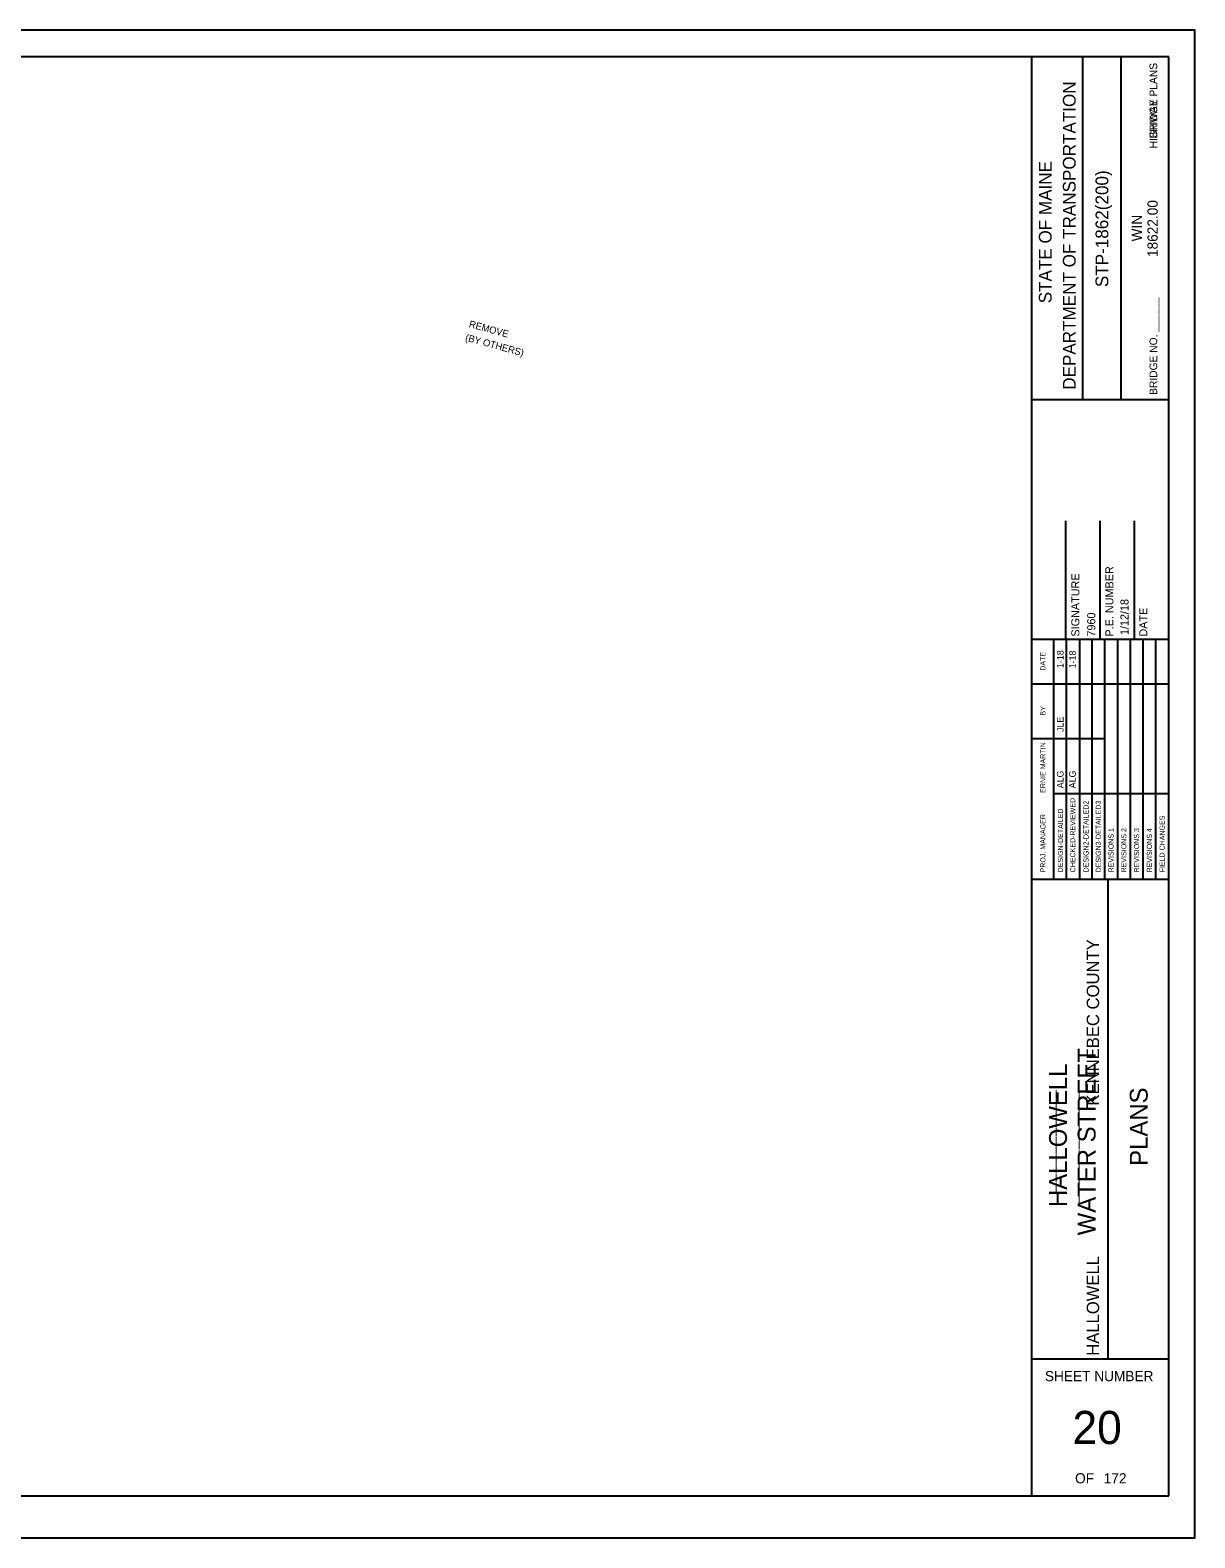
# Model space of a CAD drawing. Extents: x 0 to 850, y 0 to 550.
# Drawn here: x 425 to 850, y 0 to 550 of the extents above; entities that cross this region are included whole.
import ezdxf

# ---------------------------------------------------------------- set-up
doc = ezdxf.new("R2010")
doc.units = 0
for name, color, linetype in [('ANNOTATION', 7, 'Continuous'), ('BORDER', 7, 'Continuous'), ('BRIDGE_TITLE', 7, 'Continuous'), ('Default', 7, 'Continuous'), ('HIGHWAY_TITLE', 7, 'Continuous'), ('PLOT BOUNDARY', 7, 'Continuous')]:
    doc.layers.add(name, color=color, linetype=linetype)

msp = doc.modelspace()

# ---------------------------------------------------------------- linework, layer by layer
at = {"layer": 'BORDER'}
for p, q in [((840.33, 540.24), (40.33, 540.24)), ((790.33, 15.26), (790.33, 540.26)), ((808.97, 415.23), (808.97, 540.23)), ((822.95, 415.23), (822.95, 540.23)), ((840.33, 15.26), (840.33, 540.26)), ((790.34, 415.22), (840.33, 415.22)), ((802.83, 327.76), (802.83, 371)), ((815.33, 327.76), (815.33, 371)), ((827.83, 327.76), (827.83, 371)), ((790.33, 327.76), (840.33, 327.76)), ((790.33, 240.26), (840.33, 240.26)), ((818.29, 65.26), (818.29, 240.26)), ((790.33, 65.26), (840.33, 65.26)), ((40.33, 15.24), (840.33, 15.24))]:
    msp.add_line(p, q, dxfattribs=at)
for points in [[(798.41, 311.51), (798.41, 327.76)], [(803.07, 240.27), (803.07, 327.76)], [(807.73, 327.76), (807.73, 240.27)], [(812.39, 240.27), (812.39, 327.76)], [(817.04, 240.27), (817.04, 327.76)], [(821.7, 240.27), (821.7, 327.76)], [(826.36, 240.27), (826.36, 327.76)], [(831.02, 240.27), (831.02, 327.76)], [(835.68, 240.27), (835.68, 327.76)], [(798.41, 240.27), (798.41, 324.23)], [(790.33, 311.51), (840.33, 311.51)], [(790.33, 291.51), (798.41, 291.51)], [(798.41, 291.51), (817.04, 291.51)], [(798.41, 271.51), (840.33, 271.51)]]:
    msp.add_lwpolyline(points, dxfattribs=at)
at = {"layer": 'Default'}
msp.add_lwpolyline([(40.33, 15.24), (790.33, 15.24), (790.33, 540.26), (40.33, 540.26)], close=True, dxfattribs=at)
at = {"layer": 'PLOT BOUNDARY'}
msp.add_lwpolyline([(-0.13, -0.05), (849.87, -0.05), (849.87, 549.95), (-0.13, 549.95)], close=True, dxfattribs=at)

# ---------------------------------------------------------------- texts
at = {"layer": 'ANNOTATION'}
for s, p in [('REMOVE', (584.78, 441.66)), ('(BY OTHERS)', (583.44, 436.73))]:
    msp.add_text(s, height=2.55, rotation=344.7241, dxfattribs=at).set_placement(p)
at = {"layer": 'BORDER'}
for s, height, p in [('DEPARTMENT OF TRANSPORTATION', 4.6588, (806.37, 418.77)), ('STATE OF MAINE', 4.6588, (797.61, 450.3)), ('STP-1862(200)', 4.6588, (818.29, 456.21)), ('18622.00', 3.726, (836.31, 467.18)), ('WIN', 3.726, (830.52, 472.89)), ('P.E. NUMBER', 2.9528, (820.14, 328.72)), ('SIGNATURE', 2.953, (807.73, 328.72)), ('1/12/18', 2.953, (825.66, 329.26)), ('7960', 2.953, (813.54, 328.72)), ('DATE', 2.953, (832.54, 328.72)), ('DATE', 1.857, (795.35, 316.29)), ('1-18', 2.423, (801.95, 317.25)), ('1-18', 2.423, (806.42, 317.14)), ('BY', 1.857, (795.35, 299.93)), ('JLE', 2.423, (801.95, 293.93)), ('ERNIE MARTIN', 1.8637, (795.35, 271.72)), ('ALG', 2.423, (801.95, 273.38)), ('ALG', 2.423, (806.42, 273.38)), ('DESIGN-DETAILED', 1.8637, (801.76, 242.7)), ('CHECKED-REVIEWED', 1.8637, (806.24, 242.7)), ('DESIGN2-DETAILED2', 1.8637, (811.08, 242.7)), ('DESIGN3-DETAILED3', 1.8637, (815.55, 242.7)), ('PROJ. MANAGER', 1.8637, (795.35, 242.7)), ('FIELD CHANGES', 1.8637, (838.85, 242.7)), ('REVISIONS 1', 1.8637, (820.21, 242.7)), ('REVISIONS 2', 1.8637, (824.87, 242.7)), ('REVISIONS 3', 1.8637, (829.53, 242.7)), ('REVISIONS 4', 1.8637, (834.19, 242.7)), ('PLANS', 6.521, (832.66, 135.64))]:
    msp.add_text(s, height=height, rotation=90, dxfattribs=at).set_placement(p)
for s, height, p in [('SHEET NUMBER', 3.7264, (795.16, 57.08)), ('20', 12.097, (805.21, 34.16)), ('OF', 3.726, (806.17, 19.81)), ('172', 3.726, (816.61, 19.81))]:
    msp.add_text(s, height=height, dxfattribs=at).set_placement(p)
at = {"layer": 'BRIDGE_TITLE'}
for s, height, p in [('BRIDGE PLANS', 2.795, (836.12, 510.37)), ('BRIDGE NO. ______', 2.795, (836.12, 416.9)), ('KENNEBEC COUNTY', 4.5358, (814.93, 157.65)), ('_____________', 4.5358, (806.55, 121.2)), ('___________', 4.5358, (798.16, 126.17)), ('HALLOWELL', 4.536, (814.93, 66.36))]:
    msp.add_text(s, height=height, rotation=90, dxfattribs=at).set_placement(p)
at = {"layer": 'HIGHWAY_TITLE'}
for s, height, p in [('HIGHWAY PLANS', 2.795, (836.12, 506.82)), ('WATER STREET', 6.5214, (813.63, 110.3)), ('HALLOWELL', 6.521, (803.19, 120.63))]:
    msp.add_text(s, height=height, rotation=90, dxfattribs=at).set_placement(p)

doc.saveas('drawing.dxf')
